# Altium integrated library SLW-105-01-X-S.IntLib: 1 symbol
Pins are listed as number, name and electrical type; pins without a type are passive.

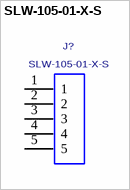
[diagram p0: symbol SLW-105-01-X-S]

## SLW-105-01-X-S
designator J?
LOW PROFILE, SINGLE ROW, 0.100"SOCKET STRIP ASSEMBLY.; MANUFACTURER: SAMTEC
footprint SLW-105-01-X-S
pins: 1, 2, 3, 4, 5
